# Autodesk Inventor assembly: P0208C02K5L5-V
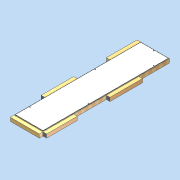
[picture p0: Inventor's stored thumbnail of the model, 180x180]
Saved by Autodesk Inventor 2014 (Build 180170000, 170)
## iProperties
Created: 2011-04
Part Number: P0208C02K5L5-V
Document SubType Name: Assembly
Designer: david.appleford
Description: 0.5w x 2w 02 Ceiling Panel - 5 Locks 5 Lugs
Mass: 32000 g
Surface Area: 38833.5 cm^2
Volume: 119248 cm^3
Density: 0.268348 g/cm^3
Cost Center: £122.00
Justset: False
Author: david.appleford
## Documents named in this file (5)
- C:\Documents and Settings\john.everitt\Local Settings\My Documents\Vault\Production MkII\VIRTUAL ELEMENTS\Virtual Ceilings\Ceiling MgO & Timber Frame\P0208C02K5L5-V.iam
- C:\Documents and Settings\john.everitt\Local Settings\My Documents\Vault\Production MkII\VIRTUAL ELEMENTS\Virtual Lugs\Superceded Lugs\LA02C3V.ipt
- C:\Documents and Settings\john.everitt\Local Settings\My Documents\Vault\Production MkII\VIRTUAL ELEMENTS\Virtual Lugs\Superceded Lugs\LA02M3V.ipt
- C:\Documents and Settings\john.everitt\Local Settings\My Documents\Vault\Production MkII\Virtual Elements\LA02E3.ipt
- C:\Documents and Settings\john.everitt\Local Settings\My Documents\Vault\Production MkII\VIRTUAL ELEMENTS\Virtual Ceilings\Ceiling MgO & Timber Frame\P0208C02K5-V.ipt
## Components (6 placed, 4 different names)
1. P0208C02K5-V:1 — Mate:1, Flush:1, Flush:2, Mate:5, Mate:6, Flush:9, Flush:10, Mate:7, Flush:11, Mate:14, Flush:12, Flush:13
2. LA02C3V:1 — Mate:1, Flush:1, Flush:2, Mate:9, Mate:13
3. LA02C3V:2 — Mate:6, Flush:9, Mate:12
4. LA02M3V:2 — Mate:5, Flush:10, Mate:12, Mate:13
5. LA02M3V:4 — Mate:7, Flush:11, Mate:9
6. LA02E3:1 — Mate:14, Flush:12, Flush:13
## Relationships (15: Mate 8, Flush 7)
- Mate:1: P0208C02K5-V:1 ↔ LA02C3V:1
- Flush:1: P0208C02K5-V:1 ↔ LA02C3V:1
- Flush:2: P0208C02K5-V:1 ↔ LA02C3V:1
- Mate:5: P0208C02K5-V:1 ↔ LA02M3V:2
- Mate:6: P0208C02K5-V:1 ↔ LA02C3V:2
- Flush:9: P0208C02K5-V:1 ↔ LA02C3V:2
- Flush:10: P0208C02K5-V:1 ↔ LA02M3V:2
- Mate:7: P0208C02K5-V:1 ↔ LA02M3V:4
- Flush:11: P0208C02K5-V:1 ↔ LA02M3V:4
- Mate:9: LA02C3V:1 ↔ LA02M3V:4
- Mate:12: LA02C3V:2 ↔ LA02M3V:2
- Mate:13: LA02C3V:1 ↔ LA02M3V:2
- Mate:14: P0208C02K5-V:1 ↔ LA02E3:1
- Flush:12: P0208C02K5-V:1 ↔ LA02E3:1
- Flush:13: P0208C02K5-V:1 ↔ LA02E3:1
## Named parameters: t = 1 mm, Cl = 2 mm
